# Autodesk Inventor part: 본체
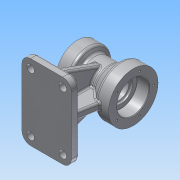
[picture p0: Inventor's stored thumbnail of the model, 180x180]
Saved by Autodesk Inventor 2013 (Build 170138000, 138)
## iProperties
Created: 2015-08
Part Number: 본체
Material: 알루미늄 6061
Document SubType Name: Modeling
Designer: Administrator
Density: 2.71 g/cm^3
Mass: 1062.79 g
Surface Area: 749.652 cm^2
Volume: 392.172 cm^3
Author: Administrator
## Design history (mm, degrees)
sketch "스케치2"
  geometry: L1 (0, 0)-(90, 0); L2 (0, 0)-(0, 35); L3 (0, 35)-(20, 35); L4 (20, 35)-(25.196, 26); L5 (25.196, 26)-(53.315, 26); L6 (53.315, 26)-(70, 40); L7 (70, 40)-(90, 40); L8 (90, 40)-(90, 0)
  constraints: 16 end point, 3 parallel, 2 perpendicular, 1 horizontal
  dimensions: "d2" = 90 distance of L1.start L1.end; "d3" = 70 diameter of L3 L1; "d5" = 80 diameter of L7 L1; "d6" = 20 distance of L2.end L3.end; "d7" = 60 deg angle of L5 L4; "d8" = 40 deg angle of L5 L6; "d9" = 20 distance of L6.end L7.end; "d11" = 52 diameter of L5 L1
revolve "회전1" sketch "스케치2" stored, may be unused: angle "d12" = 90 deg
sketch "스케치4"
  geometry: L1 (-61, -78)-(61, -78); L2 (61, -78)-(61, -90); L3 (61, -90)-(-61, -90); L4 (-61, -90)-(-61, -78); C1 r 35 at (0, 0) reference; 1 further point
  constraints: 8 end point, 2 parallel, 1 horizontal, 1 midpoint, 1 perpendicular, 1 vertical alignment
  dimensions: "d15" = 12 distance of L1.end L2.end; "d17" = 90 distance from line of L3 C1.centre; "d18" = 122 distance of L2.end L3.end
extrude "돌출1" join sketch "스케치4" distance "d19" = 80; taper "d20" = 0 deg
sketch "스케치5"
  geometry: C1 r 40 at (0, 0) reference; C2 r 26 at (0, 0)
  constraints: 1 centre point, 1 coincident
  dimensions: "d21" = 52 diameter of C2
extrude "돌출2" cut sketch "스케치5" distance "d22" = 20; taper "d23" = 0 deg
sketch "스케치6"
  geometry: C1 r 26 at (0, 0) reference; C2 r 19 at (0, 0)
  constraints: 1 centre point, 1 coincident
  dimensions: "d24" = 38 diameter of C2
extrude "돌출3" cut sketch "스케치6" distance "d25" = 3; taper "d26" = 0 deg
sketch "스케치7"
  geometry: C1 r 35 at (0, 0) reference; C2 r 20 at (0, 0)
  constraints: 1 centre point, 1 coincident
  dimensions: "d27" = 40 diameter of C2
extrude "돌출4" cut sketch "스케치7" distance "d28" = 17; taper "d29" = 0 deg
sketch "스케치8"
  geometry: C1 r 20 at (0, 0) reference; C2 r 16 at (0, 0)
  constraints: 1 centre point, 1 coincident
  dimensions: "d30" = 32 diameter of C2
extrude "돌출5" cut sketch "스케치8" stored distance "d31" = 17; taper "d32" = 0 deg
node "작업 평면1"
sketch "스케치10"
  geometry: L1 (61, -78)-(61, -90) reference; L2 (61, -90)-(-61, -90) reference; L3 (-61, -90)-(-61, -78) reference; L4 (-61, -78)-(61, -78) reference; L5 (61, -78)-(61, -90) reference; L6 (61, -90)-(-61, -90) reference; L7 (-61, -90)-(-61, -78) reference; L8 (-61, -78)-(61, -78) reference; L9 (-25.091, -6.815)-(-51, -78); L10 (25.091, -6.815)-(51, -78); C1 r 16 at (0, 0) reference; C2 r 26 at (0, 0) reference; C3 r 16 at (0, 0) reference; C4 r 35 at (0, 0) reference; A1 r 26 centre (0, 0) between (-25.091, -6.815) and (25.091, -6.815) reference; 1 further point
  constraints: 4 end point, 2 point on circle, 2 point on line, 1 equal length
  dimensions: "d33" = 70 deg angle of L4 L10; "d34" = 10 distance from line of L1 L10.end; "d35" = 70 deg angle of L4 L9
extrude "돌출6" join sketch "스케치10" stored distance "d37" = 12; taper "d38" = 0 deg
sketch "스케치11"
  geometry: L1 (90, 26)-(70, 26) reference; L2 (70, 26)-(70, 19) reference; L3 (70, 19)-(67, 19) reference; L4 (67, 19)-(67, 16) reference; L5 (67, 16)-(17, 16) reference; L6 (17, 16)-(17, 20) reference; L7 (17, 20)-(0, 20) reference; L8 (0, 20)-(0, 35) reference; L9 (0, 35)-(20, 35) reference; L10 (20, 35)-(25.196, 26) reference; L11 (25.196, 26)-(53.315, 26) reference; L12 (53.315, 26)-(70, 40) reference; L13 (70, 40)-(90, 40) reference; L14 (90, 40)-(90, 26) reference; L15 (80, -90)-(0, -90) reference; L16 (0, -90)-(0, -78) reference; L17 (0, -78)-(34, -78) reference; L18 (34, -78)-(34, -26) reference; L19 (34, -26)-(25.196, -26) reference; L20 (25.196, -26)-(20, -35) reference; L21 (20, -35)-(0, -35) reference; L22 (0, -35)-(0, -20) reference; L23 (0, -20)-(17, -20) reference; L24 (17, -20)-(17, -16) reference; L25 (17, -16)-(67, -16) reference; L26 (67, -16)-(67, -19) reference; L27 (67, -19)-(70, -19) reference; L28 (70, -19)-(70, -26) reference; L29 (70, -26)-(90, -26) reference; L30 (90, -26)-(90, -40) reference; L31 (90, -40)-(70, -40) reference; L32 (70, -40)-(53.315, -26) reference; L33 (53.315, -26)-(46, -26) reference; L34 (46, -26)-(46, -78) reference; L35 (46, -78)-(80, -78) reference; L36 (80, -78)-(80, -90) reference; L37 (76.7, -40)-(70, -78); L38 (10, -35)-(10, -78); 1 further point
  constraints: 4 end point, 3 point on line, 1 midpoint, 1 parallel
  dimensions: "d39" = 10 distance of L35.end L37.end; "d40" = 80 deg angle of L35 L37; "d41" = 10 distance between parallel lines of L16 L38
  node "절단 모서리 투영3"
feature "리브1" dims "d42" = 1, "d43" = 12, "d44" = 0, "d45" = 0, "d46" = 1, "d47" = 1
feature "리브2" dims "d48" = 1, "d49" = 12, "d50" = 0, "d51" = 0, "d52" = 1, "d53" = 1
sketch "스케치12"
  geometry: C1 r 26 at (0, 0) reference; 1 further point
  constraints: 1 vertical alignment
  dimensions: "d54" = 33 distance of C1.centre point (0, 33)
hole "구멍1" sketch "스케치12" at (0, 33) diameter "d55" = 3.242; stored, may be unused: countersink angle "d59" = 90 deg, drill point angle "d61" = 118 deg; dims "d56" = 10, "d57" = 4, "d58" = 2, "d60" = 13
sketch "스케치13"
  geometry: C1 r 20 at (0, 0) reference; 1 further point
  constraints: 1 vertical alignment
  dimensions: "d65" = 27 distance of C1.centre point (0, 27)
hole "구멍2" sketch "스케치13" at (0, 27) diameter "d66" = 3.242; stored, may be unused: countersink angle "d70" = 90 deg, drill point angle "d72" = 118 deg; dims "d67" = 10, "d68" = 4, "d69" = 2, "d71" = 13
sketch "스케치14"
  geometry: L1 (-6, -78)-(-51, -78) reference; L2 (-30, -54)-(-30, -60); L3 (-18, -54)-(-18, -60); L4 (6, -78)-(51, -78) reference; L5 (51, -78)-(61, -78) reference; L6 (61, -78)-(61, -90) reference; L7 (61, -90)-(-61, -90) reference; L8 (-61, -90)-(-61, -78) reference; L9 (-61, -78)-(-51, -78) reference; L10 (-51, -78)-(-25.091, -6.815) reference; L11 (25.091, -6.815)-(51, -78) reference; L12 (6, -25.298)-(6, -78) reference; L13 (-51, -78)-(-6, -78) reference; L14 (-6, -78)-(-6, -25.298) reference; C1 r 16 at (0, 0) reference; A1 r 26 centre (0, 0) between (-25.091, -6.815) and (-6, -25.298) reference; A2 r 6 centre (-24, -54) between (-18, -54) and (-30, -54); A3 r 6 centre (-24, -60) between (-30, -60) and (-18, -60); A4 r 26 centre (0, 0) between (25.091, -6.815) and (-25.091, -6.815) reference; A5 r 26 centre (0, 0) between (6, -25.298) and (25.091, -6.815) reference; A6 r 26 centre (0, 0) between (-25.091, -6.815) and (-6, -25.298) reference
  constraints: 4 end point, 4 point on circle, 2 centre point, 2 tangent, 1 parallel, 1 vertical alignment
  dimensions: "d76" = 12 diameter of A2; "d77" = 12 diameter of A3; "d78" = 18 dimension on A3 A2; "d79" = 24 horizontal distance of A1.centre A3.centre; "d80" = 18 distance from line of L1 A3.centre; "d81" = 6 distance of L2.end L2.start
extrude "돌출7" cut sketch "스케치14" stored distance "d82" = 12; taper "d83" = 0 deg
sketch "스케치15"
  geometry: L1 (0, 0)-(0, 43.518) reference; L2 (-10, -12)-(70, -12) reference; L3 (-10, 0)-(70, 0) reference; 2 further points
  constraints: 1 other
  dimensions: "d84" = 16 distance from line of point (16, 24) L1; "d86" = 24 distance from line of L3 point (16, 24)
feature "엠보싱1" sketch "스케치15" dims "d2" = 90, "d3" = 70, "d5" = 80, "d6" = 20, "d7" = 60 deg, "d8" = 40 deg, "d9" = 20, "d11" = 52, "d87" = 0.5, "d88" = 0
chamfer "모따기1" distance "d89" = 1; stored, may be unused: second distance "d90" = 2, angle "d91" = 45 deg
fillet "모깎기1" dims "d92" = 3
fillet "모깎기2" dims "d93" = 0.3
fillet "모깎기3" dims "d94" = 5
fillet "모깎기4" dims "d95" = 14
sketch "스케치16"
  geometry: L1 (14, -14)-(66, -14) reference; L2 (80, 94)-(80, 0) reference; L3 (46, 53)-(70, 53) reference; L4 (14, 0)-(66, 0); L5 (66, 94)-(66, 0); C1 r 6 at (66, 0); C2 r 6 at (66, 94); C3 r 6 at (14, 94); C4 r 6 at (14, 0); 5 further points
  constraints: 4 centre point, 4 end point, 4 midpoint, 3 horizontal alignment, 3 vertical alignment, 1 parallel, 1 perpendicular
  dimensions: "d96" = 12 diameter of C1; "d97" = 12 diameter of C2; "d98" = 12 diameter of C3; "d99" = 12 diameter of C4; "d100" = 52 distance of L4.end L4.start; "d101" = 94 distance of L4.end L5.start
extrude "돌출8" cut sketch "스케치16" stored distance "d102" = 12; taper "d103" = 0 deg
fillet "모깎기5" dims "d104" = 3
fillet "모깎기6" dims "d105" = 3
fillet "모깎기7" dims "d106" = 3
fillet "모깎기8" dims "d107" = 3
node "솔리드1"
pattern_circular "원형 패턴1" dims angle "d63" = 360 deg
pattern_circular "원형 패턴2" dims angle "d74" = 360 deg
mirror "대칭1"
node "절단 모서리 투영1"
node "절단 모서리 투영2"
node "절단 모서리 투영4"
